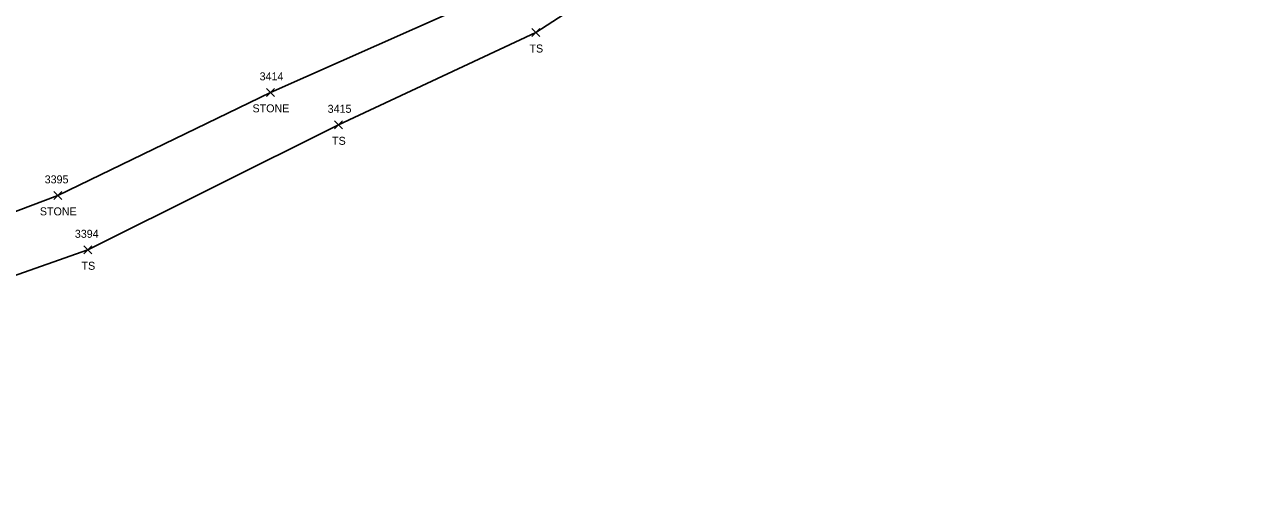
# Model space of a CAD drawing. Extents: x 1623612 to 1625808, y 621345 to 627748.
# Drawn here: x 1625229.6 to 1625536.7, y 626780.7 to 626896.7 of the extents above; entities that cross this region are included whole.
import ezdxf

# ---------------------------------------------------------------- set-up
doc = ezdxf.new("R2010")
doc.units = 0
for name, color, linetype in [('L_A', 7, 'Continuous'), ('L_I', 7, 'Continuous'), ('L_TIC', 7, 'Continuous'), ('LASF', 7, 'Continuous'), ('LELB', 7, 'Continuous'), ('LSOGP', 7, 'Continuous')]:
    doc.layers.add(name, color=color, linetype=linetype)

msp = doc.modelspace()

# ---------------------------------------------------------------- linework, layer by layer
at = {"layer": 'L_TIC'}
for points in [[(1625356.38, 626893.72), (1625358.38, 626895.72)], [(1625358.38, 626893.72), (1625356.38, 626895.72)], [(1625290.03, 626878.76), (1625292.03, 626880.76)], [(1625292.03, 626878.76), (1625290.03, 626880.76)], [(1625307.04, 626870.64), (1625309.04, 626872.64)], [(1625309.04, 626870.64), (1625307.04, 626872.64)], [(1625236.88, 626853), (1625238.88, 626855)], [(1625238.88, 626853), (1625236.88, 626855)], [(1625244.42, 626839.4), (1625246.42, 626841.4)], [(1625246.42, 626839.4), (1625244.42, 626841.4)]]:
    msp.add_lwpolyline(points, dxfattribs=at)
at = {"layer": 'LASF'}
msp.add_lwpolyline([(1625160.13, 626885.56), (1625166.23, 626871.01), (1625184.49, 626848.17), (1625202.58, 626840.63), (1625237.88, 626854), (1625291.03, 626879.76), (1625353.61, 626907.53), (1625390.22, 626926.27), (1625415.04, 626948.64), (1625407.28, 626970.97)], dxfattribs=at)
at = {"layer": 'LELB'}
msp.add_lwpolyline([(1625083.53, 626780.74), (1625137.04, 626804.12), (1625178.43, 626816.77), (1625245.42, 626840.4), (1625308.04, 626871.64), (1625357.38, 626894.72), (1625395.36, 626919.42), (1625409.95, 626928.75), (1625453.5, 626946.29), (1625490.76, 626971.58), (1625536.74, 626991.35)], dxfattribs=at)
at = {"layer": 'LSOGP'}
msp.add_lwpolyline([(1625178.43, 626816.77), (1625245.42, 626840.4), (1625308.04, 626871.64), (1625357.38, 626894.72), (1625395.36, 626919.42)], dxfattribs=at)

# ---------------------------------------------------------------- texts
at = {"layer": 'L_A'}
for s, p in [('TS', (1625355.79, 626889.72)), ('STONE', (1625286.57, 626874.76)), ('TS', (1625306.45, 626866.64)), ('STONE', (1625233.42, 626849)), ('TS', (1625243.83, 626835.4))]:
    msp.add_text(s, height=2, dxfattribs=at).set_placement(p)
at = {"layer": 'L_I'}
for s, p in [('3414', (1625288.34, 626882.76)), ('3415', (1625305.35, 626874.64)), ('3395', (1625234.62, 626857)), ('3394', (1625242.16, 626843.4))]:
    msp.add_text(s, height=2, dxfattribs=at).set_placement(p)

doc.saveas('drawing.dxf')
